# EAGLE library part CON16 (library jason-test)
16-pin connector
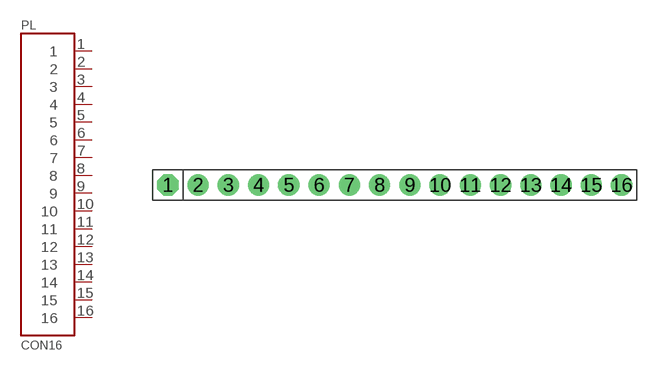
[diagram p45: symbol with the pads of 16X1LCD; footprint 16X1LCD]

Designator prefix PL

## CON16  [16X1LCD]
1  1
2  2
3  3
4  4
5  5
6  6
7  7
8  8
9  9
10  10
11  11
12  12
13  13
14  14
15  15
16  16

## Footprint 16X1LCD (pad centres in mm)
drill 1 pad 1.778 octagon: 1 -19.05,0
drill 1 pad 1.778 round: 2 -16.51,0; 3 -13.97,0; 4 -11.43,0; 5 -8.89,0; 6 -6.35,0; 7 -3.81,0; 8 -1.27,0; 9 1.27,0; 10 3.81,0; 11 6.35,0; 12 8.89,0; 13 11.43,0; 14 13.97,0; 15 16.51,0; 16 19.05,0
